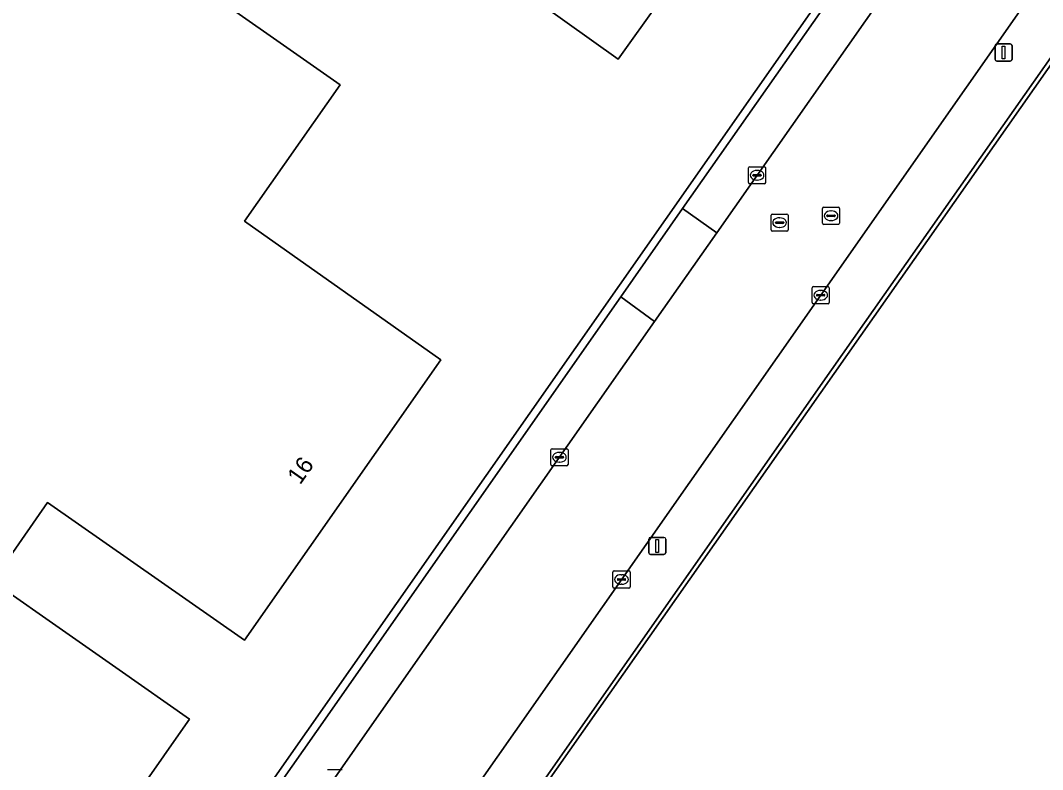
# Model space of a CAD drawing. Extents: x 155018 to 156648, y 383979 to 385733.
# Drawn here: x 155561.5 to 155621.1, y 384747.8 to 384791.5 of the extents above; entities that cross this region are included whole.
import ezdxf

# ---------------------------------------------------------------- set-up
doc = ezdxf.new("R2010")
doc.units = 0
for name, color, linetype in [('IMGEO_Erf', 7, 'Continuous'), ('IMGEO_Groenvoorziening', 7, 'Continuous'), ('IMGEO_Hek', 7, 'Continuous'), ('IMGEO_Kolk', 7, 'Continuous'), ('IMGEO_Lichtmast', 7, 'Continuous'), ('IMGEO_Pand', 7, 'Continuous'), ('IMGEO_Pand_nummerreeks', 7, 'Continuous'), ('IMGEO_Parkeervlak_open', 7, 'Continuous'), ('IMGEO_Rijbaan_lokaal_gesloten', 7, 'Continuous'), ('IMGEO_Rioolput', 7, 'Continuous'), ('IMGEO_Voetpad_open', 7, 'Continuous')]:
    doc.layers.add(name, color=color, linetype=linetype)

msp = doc.modelspace()

# ---------------------------------------------------------------- linework, layer by layer
at = {"layer": 'IMGEO_Erf'}
for points in [[(155667.02, 384853.625), (155588.106, 384741.158), (155588.217, 384741.112), (155586.789, 384739.087), (155582.631, 384733.19), (155582.416, 384732.885), (155582.316, 384732.95), (155581.815, 384732.239), (155580.185, 384729.709), (155581.396, 384728.861), (155583.799, 384727.241), (155587.677, 384724.525), (155589.403, 384726.99), (155674.514, 384667.39), (155696.402, 384652.063), (155846.077, 384718.2), (155848.294, 384719.15), (155855.39, 384722.112), (155860.344, 384724.18), (155861.71, 384724.75), (155868.424, 384727.546), (155868.337, 384727.731), (155875.618, 384730.752), (155882.777, 384733.722)], [(155553.633, 384715.232), (155553.739, 384715.172), (155553.747, 384715.183), (155566.056, 384732.66), (155578.198, 384750), (155612.129, 384798.458), (155612.508, 384798.198), (155616.168, 384803.406), (155615.737, 384803.696), (155649.459, 384851.832), (155649.247, 384851.98)]]:
    msp.add_lwpolyline(points, dxfattribs=at)
for points in [[(155547.35, 384810.655), (155576.058, 384790.588), (155580.154, 384787.72), (155574.557, 384779.779), (155586.015, 384771.676), (155574.573, 384755.332), (155563.08, 384763.359), (155560.734, 384760.001), (155556.634, 384762.863), (155527.932, 384782.896)], [(155586.573, 384801.243), (155598.747, 384792.566), (155596.367, 384789.227), (155584.193, 384797.904)], [(155567.254, 384753.592), (155571.349, 384750.724), (155570.843, 384750), (155551.094, 384721.759), (155550.46, 384722.203), (155548.26, 384719.057), (155548.864, 384718.635), (155545.279, 384713.508), (155520.268, 384730.998), (155523.134, 384735.096), (155528.902, 384743.323), (155516.799, 384751.818), (155534.25, 384776.701), (155546.358, 384768.223)]]:
    msp.add_lwpolyline(points, close=True, dxfattribs=at)
at = {"layer": 'IMGEO_Groenvoorziening'}
msp.add_lwpolyline([(155667.02, 384853.625), (155667.198, 384853.508), (155669.212, 384856.331), (155669.497, 384856.797), (155668.817, 384856.954), (155660.389, 384844.659), (155636.862, 384811.074), (155608.808, 384771.107), (155594.019, 384750), (155586.655, 384739.49), (155582.342, 384733.152), (155582.316, 384732.95), (155582.416, 384732.885), (155582.631, 384733.19), (155586.789, 384739.087), (155588.217, 384741.112), (155588.106, 384741.158)], close=True, dxfattribs=at)
at = {"layer": 'IMGEO_Hek'}
msp.add_lwpolyline([(155586.789, 384739.087), (155588.217, 384741.112), (155588.106, 384741.158), (155667.02, 384853.625), (155667.198, 384853.508), (155669.212, 384856.331)], dxfattribs=at)
at = {"layer": 'IMGEO_Kolk'}
for p, q in [((155603.961, 384782.021), (155603.961, 384782.873)), ((155604.036, 384782.947), (155604.888, 384782.947)), ((155604.449, 384782.727), (155604.474, 384782.727)), ((155604.962, 384782.873), (155604.962, 384782.021)), ((155604.22, 384782.441), (155604.22, 384782.453)), ((155604.658, 384782.404), (155604.26, 384782.404)), ((155604.263, 384782.49), (155604.661, 384782.49)), ((155604.472, 384782.167), (155604.447, 384782.167)), ((155604.704, 384782.453), (155604.704, 384782.441)), ((155604.888, 384781.947), (155604.036, 384781.947)), ((155607.671, 384775.025), (155607.671, 384775.877)), ((155607.746, 384775.951), (155608.598, 384775.951)), ((155608.159, 384775.731), (155608.184, 384775.731)), ((155608.672, 384775.877), (155608.672, 384775.025)), ((155607.93, 384775.445), (155607.93, 384775.457)), ((155608.368, 384775.408), (155607.97, 384775.408)), ((155607.973, 384775.494), (155608.371, 384775.494)), ((155608.182, 384775.171), (155608.157, 384775.171)), ((155608.414, 384775.457), (155608.414, 384775.445)), ((155608.598, 384774.951), (155607.746, 384774.951)), ((155592.434, 384765.572), (155592.434, 384766.424)), ((155592.509, 384766.498), (155593.361, 384766.498)), ((155592.736, 384766.041), (155593.134, 384766.041)), ((155592.922, 384766.278), (155592.947, 384766.278)), ((155593.435, 384766.424), (155593.435, 384765.572)), ((155593.361, 384765.498), (155592.509, 384765.498)), ((155592.693, 384765.992), (155592.693, 384766.004)), ((155593.131, 384765.955), (155592.733, 384765.955)), ((155592.945, 384765.718), (155592.92, 384765.718)), ((155593.177, 384766.004), (155593.177, 384765.992)), ((155596.054, 384758.444), (155596.054, 384759.296)), ((155596.129, 384759.37), (155596.981, 384759.37)), ((155596.313, 384758.864), (155596.313, 384758.876)), ((155596.356, 384758.913), (155596.754, 384758.913)), ((155596.542, 384759.15), (155596.567, 384759.15)), ((155596.797, 384758.876), (155596.797, 384758.864)), ((155597.055, 384759.296), (155597.055, 384758.444)), ((155596.981, 384758.37), (155596.129, 384758.37)), ((155596.751, 384758.827), (155596.353, 384758.827)), ((155596.565, 384758.59), (155596.54, 384758.59)), ((155579.401, 384747.782), (155580.253, 384747.782))]:
    msp.add_line(p, q, dxfattribs=at)
for points in [[(155603.961, 384782.021), (155603.961, 384782.873)], [(155604.036, 384782.947), (155604.888, 384782.947)], [(155604.962, 384782.873), (155604.962, 384782.021)], [(155604.888, 384781.947), (155604.036, 384781.947)], [(155607.671, 384775.025), (155607.671, 384775.877)], [(155607.746, 384775.951), (155608.598, 384775.951)], [(155608.672, 384775.877), (155608.672, 384775.025)], [(155608.598, 384774.951), (155607.746, 384774.951)], [(155592.434, 384765.572), (155592.434, 384766.424)], [(155592.509, 384766.498), (155593.361, 384766.498)], [(155593.435, 384766.424), (155593.435, 384765.572)], [(155593.361, 384765.498), (155592.509, 384765.498)], [(155596.054, 384758.444), (155596.054, 384759.296)], [(155596.129, 384759.37), (155596.981, 384759.37)], [(155597.055, 384759.296), (155597.055, 384758.444)], [(155596.981, 384758.37), (155596.129, 384758.37)], [(155579.401, 384747.782), (155580.253, 384747.782)]]:
    msp.add_lwpolyline(points, dxfattribs=at)
for centre, radius, start, end in [((155604.038, 384782.871), 0.0765, 91.55205, 178.44795), ((155604.038, 384782.871), 0.0765, 91.55205, 178.44795), ((155604.886, 384782.871), 0.0765, 1.55205, 88.44795), ((155604.886, 384782.871), 0.0765, 1.55205, 88.44795), ((155604.26, 384782.45), 0.0403, 85.87752, 175.75265), ((155604.257, 384782.44), 0.0366, 178.93798, 274.71019), ((155604.661, 384782.447), 0.043, 264.86636, 352.45326), ((155604.665, 384782.452), 0.0386, 1.73085, 96.63898), ((155604.038, 384782.023), 0.0765, 181.55205, 268.44795), ((155604.038, 384782.023), 0.0765, 181.55205, 268.44795), ((155604.886, 384782.023), 0.0765, 271.55205, 358.44795), ((155604.886, 384782.023), 0.0765, 271.55205, 358.44795), ((155607.748, 384775.875), 0.0765, 91.55205, 178.44795), ((155607.748, 384775.875), 0.0765, 91.55205, 178.44795), ((155608.596, 384775.875), 0.0765, 1.55205, 88.44795), ((155608.596, 384775.875), 0.0765, 1.55205, 88.44795), ((155607.748, 384775.027), 0.0765, 181.55205, 268.44795), ((155607.748, 384775.027), 0.0765, 181.55205, 268.44795), ((155607.97, 384775.454), 0.0403, 85.87752, 175.75265), ((155607.967, 384775.444), 0.0366, 178.93798, 274.71019), ((155608.371, 384775.451), 0.043, 264.86636, 352.45326), ((155608.375, 384775.456), 0.0386, 1.73085, 96.63898), ((155608.596, 384775.027), 0.0765, 271.55205, 358.44795), ((155608.596, 384775.027), 0.0765, 271.55205, 358.44795), ((155592.511, 384766.422), 0.0765, 91.55205, 178.44795), ((155592.511, 384766.422), 0.0765, 91.55205, 178.44795), ((155592.733, 384766.001), 0.0403, 85.87752, 175.75265), ((155593.138, 384766.003), 0.0386, 1.73085, 96.63898), ((155593.359, 384766.422), 0.0765, 1.55205, 88.44795), ((155593.359, 384766.422), 0.0765, 1.55205, 88.44795), ((155592.511, 384765.574), 0.0765, 181.55205, 268.44795), ((155592.511, 384765.574), 0.0765, 181.55205, 268.44795), ((155592.73, 384765.991), 0.0366, 178.93798, 274.71019), ((155593.134, 384765.998), 0.043, 264.86636, 352.45326), ((155593.359, 384765.574), 0.0765, 271.55205, 358.44795), ((155593.359, 384765.574), 0.0765, 271.55205, 358.44795), ((155596.131, 384759.294), 0.0765, 91.55205, 178.44795), ((155596.131, 384759.294), 0.0765, 91.55205, 178.44795), ((155596.353, 384758.873), 0.0403, 85.87752, 175.75265), ((155596.758, 384758.875), 0.0386, 1.73085, 96.63898), ((155596.979, 384759.294), 0.0765, 1.55205, 88.44795), ((155596.979, 384759.294), 0.0765, 1.55205, 88.44795), ((155596.131, 384758.446), 0.0765, 181.55205, 268.44795), ((155596.131, 384758.446), 0.0765, 181.55205, 268.44795), ((155596.35, 384758.863), 0.0366, 178.93798, 274.71019), ((155596.754, 384758.87), 0.043, 264.86636, 352.45326), ((155596.979, 384758.446), 0.0765, 271.55205, 358.44795), ((155596.979, 384758.446), 0.0765, 271.55205, 358.44795)]:
    msp.add_arc(centre, radius, start, end, dxfattribs=at)
for centre, major_axis, ratio, start_param, end_param in [((155604.448, 384782.447), (-0.387, 0.002), 0.722429, 4.712389, 7.853982), ((155604.473, 384782.447), (-0.39, 0.002), 0.717154, 1.570796, 4.712389), ((155608.158, 384775.451), (-0.387, 0.002), 0.722429, 4.712389, 7.853982), ((155608.183, 384775.451), (-0.39, 0.002), 0.717154, 1.570796, 4.712389), ((155592.921, 384765.998), (-0.387, 0.002), 0.722429, 4.712389, 7.853982), ((155592.946, 384765.998), (-0.39, 0.002), 0.717154, 1.570796, 4.712389), ((155596.541, 384758.87), (-0.387, 0.002), 0.722429, 4.712389, 7.853982), ((155596.566, 384758.87), (-0.39, 0.002), 0.717154, 1.570796, 4.712389)]:
    msp.add_ellipse(centre, major_axis=major_axis, ratio=ratio, start_param=start_param, end_param=end_param, dxfattribs=at)
at = {"layer": 'IMGEO_Lichtmast'}
for p, q in [((155618.342, 384789.208), (155618.342, 384790.008)), ((155618.342, 384790.008), (155618.342, 384789.208)), ((155618.442, 384790.108), (155619.232, 384790.108)), ((155619.232, 384790.108), (155618.442, 384790.108)), ((155619.332, 384790.008), (155619.332, 384789.208)), ((155619.332, 384789.208), (155619.332, 384790.008)), ((155619.232, 384789.108), (155618.442, 384789.108)), ((155618.442, 384789.108), (155619.232, 384789.108)), ((155598.24, 384761.327), (155599.03, 384761.327)), ((155599.03, 384761.327), (155598.24, 384761.327)), ((155598.14, 384760.427), (155598.14, 384761.227)), ((155598.14, 384761.227), (155598.14, 384760.427)), ((155599.13, 384761.227), (155599.13, 384760.427)), ((155599.13, 384760.427), (155599.13, 384761.227)), ((155599.03, 384760.327), (155598.24, 384760.327)), ((155598.24, 384760.327), (155599.03, 384760.327))]:
    msp.add_line(p, q, dxfattribs=at)
for points in [[(155618.762, 384789.983), (155618.912, 384789.983), (155618.912, 384789.233), (155618.762, 384789.233), (155618.762, 384789.983)], [(155598.56, 384761.202), (155598.71, 384761.202), (155598.71, 384760.452), (155598.56, 384760.452), (155598.56, 384761.202)]]:
    msp.add_lwpolyline(points, dxfattribs=at)
for centre, start, end in [((155618.442, 384790.008), 90, 180), ((155618.442, 384790.008), 90, 180), ((155619.232, 384790.008), 0, 90), ((155619.232, 384790.008), 360, 90), ((155618.442, 384789.208), 180, 270), ((155618.442, 384789.208), 180, 270), ((155619.232, 384789.208), 270, 0), ((155619.232, 384789.208), 270, 0), ((155598.24, 384761.227), 90, 180), ((155598.24, 384761.227), 90, 180), ((155599.03, 384761.227), 0, 90), ((155599.03, 384761.227), 360, 90), ((155598.24, 384760.427), 180, 270), ((155598.24, 384760.427), 180, 270), ((155599.03, 384760.427), 270, 0), ((155599.03, 384760.427), 270, 0)]:
    msp.add_arc(centre, 0.1, start, end, dxfattribs=at)
at = {"layer": 'IMGEO_Pand'}
for points in [[(155527.932, 384782.896), (155556.634, 384762.863), (155560.734, 384760.001), (155563.08, 384763.359), (155574.573, 384755.332), (155586.015, 384771.676), (155574.557, 384779.779), (155580.154, 384787.72), (155576.058, 384790.588), (155547.35, 384810.655)], [(155596.367, 384789.227), (155598.747, 384792.566), (155586.573, 384801.243), (155584.193, 384797.904)], [(155570.843, 384750), (155571.349, 384750.724), (155567.254, 384753.592), (155546.358, 384768.223), (155534.25, 384776.701), (155516.799, 384751.818), (155528.902, 384743.323), (155523.134, 384735.096), (155520.268, 384730.998), (155545.279, 384713.508), (155548.864, 384718.635), (155548.26, 384719.057), (155550.46, 384722.203), (155551.094, 384721.759)]]:
    msp.add_lwpolyline(points, close=True, dxfattribs=at)
at = {"layer": 'IMGEO_Parkeervlak_open'}
for points in [[(155600.119, 384780.503), (155602.107, 384779.088), (155613.015, 384794.672), (155612.249, 384795.277), (155611.036, 384796.09)], [(155573.395, 384738.09), (155581.725, 384750), (155598.478, 384773.909), (155596.516, 384775.358), (155578.755, 384750), (155571.397, 384739.494)]]:
    msp.add_lwpolyline(points, close=True, dxfattribs=at)
at = {"layer": 'IMGEO_Rijbaan_lokaal_gesloten'}
for points in [[(155557.839, 384704.064), (155557.967, 384704.242), (155558.339, 384703.973), (155565.165, 384713.55), (155573.586, 384725.999), (155578.096, 384732.463), (155583.356, 384740.042), (155586.289, 384744.214), (155590.343, 384750), (155608.173, 384775.45), (155620.847, 384793.568), (155634.39, 384812.919), (155647.778, 384831.987), (155658, 384846.57), (155663.285, 384854.104), (155665.547, 384857.446), (155665.874, 384857.967)], [(155652.394, 384850.88), (155629.679, 384818.438), (155619.716, 384804.252), (155613.015, 384794.672), (155602.107, 384779.088), (155598.478, 384773.909), (155581.725, 384750), (155573.395, 384738.09), (155569.504, 384732.554), (155555.663, 384712.8)]]:
    msp.add_lwpolyline(points, dxfattribs=at)
at = {"layer": 'IMGEO_Rioolput'}
for p, q in [((155608.277, 384779.659), (155608.277, 384780.511)), ((155608.352, 384780.585), (155609.204, 384780.585)), ((155608.765, 384780.365), (155608.79, 384780.365)), ((155609.278, 384780.511), (155609.278, 384779.659)), ((155605.276, 384779.259), (155605.276, 384780.111)), ((155605.351, 384780.185), (155606.203, 384780.185)), ((155605.764, 384779.965), (155605.789, 384779.965)), ((155606.277, 384780.111), (155606.277, 384779.259)), ((155608.536, 384780.079), (155608.536, 384780.091)), ((155608.974, 384780.042), (155608.576, 384780.042)), ((155608.579, 384780.128), (155608.977, 384780.128)), ((155608.788, 384779.805), (155608.763, 384779.805)), ((155609.02, 384780.091), (155609.02, 384780.079)), ((155606.203, 384779.185), (155605.351, 384779.185)), ((155605.535, 384779.679), (155605.535, 384779.691)), ((155605.973, 384779.642), (155605.575, 384779.642)), ((155605.578, 384779.728), (155605.976, 384779.728)), ((155605.787, 384779.405), (155605.762, 384779.405)), ((155606.019, 384779.691), (155606.019, 384779.679)), ((155609.204, 384779.585), (155608.352, 384779.585))]:
    msp.add_line(p, q, dxfattribs=at)
for points in [[(155608.277, 384779.659), (155608.277, 384780.511)], [(155608.352, 384780.585), (155609.204, 384780.585)], [(155609.278, 384780.511), (155609.278, 384779.659)], [(155605.276, 384779.259), (155605.276, 384780.111)], [(155605.351, 384780.185), (155606.203, 384780.185)], [(155606.277, 384780.111), (155606.277, 384779.259)], [(155606.203, 384779.185), (155605.351, 384779.185)], [(155609.204, 384779.585), (155608.352, 384779.585)]]:
    msp.add_lwpolyline(points, dxfattribs=at)
for centre, radius, start, end in [((155608.354, 384780.509), 0.0765, 91.55205, 178.44795), ((155608.354, 384780.509), 0.0765, 91.55205, 178.44795), ((155609.202, 384780.509), 0.0765, 1.55205, 88.44795), ((155609.202, 384780.509), 0.0765, 1.55205, 88.44795), ((155605.353, 384780.109), 0.0765, 91.55205, 178.44795), ((155605.353, 384780.109), 0.0765, 91.55205, 178.44795), ((155606.201, 384780.109), 0.0765, 1.55205, 88.44795), ((155606.201, 384780.109), 0.0765, 1.55205, 88.44795), ((155608.576, 384780.088), 0.0403, 85.87752, 175.75265), ((155608.573, 384780.078), 0.0366, 178.93798, 274.71019), ((155608.977, 384780.085), 0.043, 264.86636, 352.45326), ((155608.981, 384780.09), 0.0386, 1.73085, 96.63898), ((155605.353, 384779.261), 0.0765, 181.55205, 268.44795), ((155605.353, 384779.261), 0.0765, 181.55205, 268.44795), ((155605.575, 384779.688), 0.0403, 85.87752, 175.75265), ((155605.572, 384779.678), 0.0366, 178.93798, 274.71019), ((155605.976, 384779.685), 0.043, 264.86636, 352.45326), ((155605.98, 384779.69), 0.0386, 1.73085, 96.63898), ((155606.201, 384779.261), 0.0765, 271.55205, 358.44795), ((155606.201, 384779.261), 0.0765, 271.55205, 358.44795), ((155608.354, 384779.661), 0.0765, 181.55205, 268.44795), ((155608.354, 384779.661), 0.0765, 181.55205, 268.44795), ((155609.202, 384779.661), 0.0765, 271.55205, 358.44795), ((155609.202, 384779.661), 0.0765, 271.55205, 358.44795)]:
    msp.add_arc(centre, radius, start, end, dxfattribs=at)
for centre, major_axis, ratio, start_param, end_param in [((155608.764, 384780.085), (-0.387, 0.002), 0.722429, 4.712389, 7.853982), ((155608.789, 384780.085), (-0.39, 0.002), 0.717154, 1.570796, 4.712389), ((155605.763, 384779.685), (-0.387, 0.002), 0.722429, 4.712389, 7.853982), ((155605.788, 384779.685), (-0.39, 0.002), 0.717154, 1.570796, 4.712389)]:
    msp.add_ellipse(centre, major_axis=major_axis, ratio=ratio, start_param=start_param, end_param=end_param, dxfattribs=at)
at = {"layer": 'IMGEO_Voetpad_open'}
for points in [[(155586.655, 384739.49), (155594.019, 384750), (155608.808, 384771.107), (155636.862, 384811.074), (155660.389, 384844.659), (155668.817, 384856.954), (155665.874, 384857.967), (155665.547, 384857.446), (155663.285, 384854.104), (155658, 384846.57), (155647.778, 384831.987), (155634.39, 384812.919), (155620.847, 384793.568), (155608.173, 384775.45), (155590.343, 384750), (155586.289, 384744.214)], [(155596.516, 384775.358), (155600.119, 384780.503), (155611.036, 384796.09), (155611.005, 384796.282), (155612.196, 384797.988), (155612.346, 384797.968), (155612.508, 384798.198), (155612.129, 384798.458), (155578.198, 384750), (155566.056, 384732.66), (155553.747, 384715.183), (155553.739, 384715.172), (155554.237, 384714.972), (155567.524, 384733.965), (155571.397, 384739.494), (155578.755, 384750)], [(155600.119, 384780.503), (155596.516, 384775.358), (155598.478, 384773.909), (155602.107, 384779.088)]]:
    msp.add_lwpolyline(points, close=True, dxfattribs=at)

# ---------------------------------------------------------------- texts
at = {"layer": 'IMGEO_Pand_nummerreeks'}
msp.add_text('16', height=1, rotation=55.00516, dxfattribs=at).set_placement((155577.808, 384764.347))

doc.saveas('drawing.dxf')
